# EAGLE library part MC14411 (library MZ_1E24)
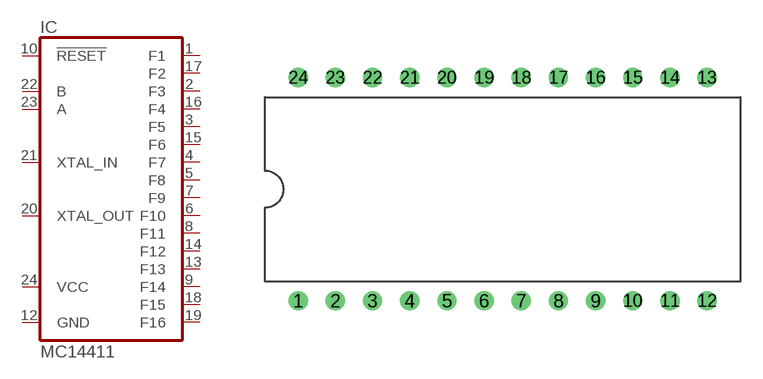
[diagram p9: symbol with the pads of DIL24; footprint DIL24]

Designator prefix IC

## MC14411  [DIL24]
1  F1  out
2  F3  out
3  F5  out
4  F7  out
5  F8  out
6  F10  out
7  F9  out
8  F11  out
9  F14  out
10  !RESET  pas
12  GND  pwr
13  F13  out
14  F12  out
15  F6  out
16  F4  out
17  F2  out
18  F15  out
19  F16  out
20  XTAL_OUT  out
21  XTAL_IN  in
22  B  in
23  A  in
24  VCC  pwr

## Footprint DIL24 (pad centres in mm)
drill 0.813 round: 1 -13.97,-7.62; 2 -11.43,-7.62; 3 -8.89,-7.62; 4 -6.35,-7.62; 5 -3.81,-7.62; 6 -1.27,-7.62; 7 1.27,-7.62; 8 3.81,-7.62; 9 6.35,-7.62; 10 8.89,-7.62; 11 11.43,-7.62; 12 13.97,-7.62; 13 13.97,7.62; 14 11.43,7.62; 15 8.89,7.62; 16 6.35,7.62; 17 3.81,7.62; 18 1.27,7.62; 19 -1.27,7.62; 20 -3.81,7.62; 21 -6.35,7.62; 22 -8.89,7.62; 23 -11.43,7.62; 24 -13.97,7.62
